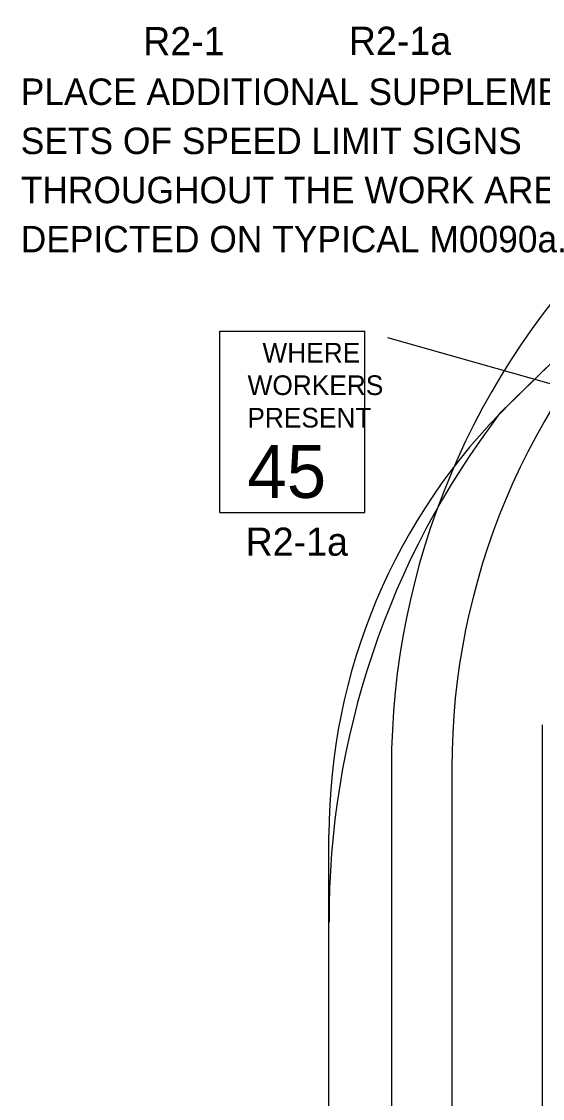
# Model space of a CAD drawing. Extents: x 16735 to 19510, y 5880 to 6929.
# Drawn here: x 16739.9 to 16877.8, y 6269.8 to 6554.7 of the extents above; entities that cross this region are included whole.
import ezdxf

# ---------------------------------------------------------------- set-up
doc = ezdxf.new("R2010")
doc.units = 0
for name, color, linetype in [('ALI_LEGAL_EX', 7, 'Continuous'), ('BORDER', 7, 'Continuous'), ('SCRATCH_LEVEL_A', 7, 'Continuous'), ('TRAFFIC_SIGNS_PR', 7, 'Continuous')]:
    doc.layers.add(name, color=color, linetype=linetype)

msp = doc.modelspace()

# ---------------------------------------------------------------- linework, layer by layer
at = {"layer": 'ALI_LEGAL_EX'}
for p, q in [((16866.49, 6450.99), (17215.7, 6793.27)), ((16821.31, 5959.79), (16821.31, 6316.41))]:
    msp.add_line(p, q, dxfattribs=at)
msp.add_arc((17042.09, 6317.17), 220.78, 142.6899, 180.1983, dxfattribs=at)
at = {"layer": 'BORDER'}
for p, q in [((16867.78, 6452.26), (17214.45, 6792.05)), ((16837.83, 6357.23), (16837.83, 5977.53)), ((16853.83, 6357.23), (16853.83, 5977.53)), ((16821.31, 5959.79), (16821.31, 6339.5)), ((16877.83, 5977.53), (16877.83, 6334.14))]:
    msp.add_line(p, q, dxfattribs=at)
for points in [[(16877.83, 6277.53), (16877.83, 6368.68)], [(16877.83, 6277.53), (16877.83, 6302.53)]]:
    msp.add_lwpolyline(points, dxfattribs=at)
for centre, radius, start, end in [((17037.83, 6357.23), 200, 134.4258, 179.9999), ((17037.83, 6357.23), 184, 134.4258, 180.0001), ((16981.31, 6339.5), 160, 134.3562, 180.0001)]:
    msp.add_arc(centre, radius, start, end, dxfattribs=at)
at = {"layer": 'SCRATCH_LEVEL_A'}
for p, q in [((16792.38, 6472.83), (16830.78, 6472.83)), ((16792.38, 6424.83), (16792.38, 6472.83)), ((16830.78, 6424.83), (16830.78, 6472.83)), ((16792.38, 6424.83), (16830.78, 6424.83))]:
    msp.add_line(p, q, dxfattribs=at)
at = {"layer": 'TRAFFIC_SIGNS_PR'}
msp.add_line((16953.87, 6437.75), (16836.92, 6471.08), dxfattribs=at)

# ---------------------------------------------------------------- texts
at = {"layer": 'SCRATCH_LEVEL_A'}
for s, height, p in [('R2-1', 7.44, (16772.11, 6545.84)), ('R2-1a', 7.44, (16826.55, 6545.93)), ('PLACE ADDITIONAL SUPPLEMENTAL', 7, (16739.7, 6532.67)), ('SETS OF SPEED LIMIT SIGNS', 7, (16739.7, 6519.67)), ('THROUGHOUT THE WORK AREA AS', 7, (16739.7, 6506.67)), ('DEPICTED ON TYPICAL M0090a.', 7, (16739.7, 6493.67)), ('WHERE', 5.2, (16803.69, 6464.51)), ('WORKERS', 5.2, (16799.76, 6455.91)), ('PRESENT', 5.2, (16799.7, 6447.31)), ('45', 14.031, (16799.69, 6428.68)), ('R2-1a', 7.44, (16799.23, 6413.39))]:
    msp.add_text(s, height=height, dxfattribs=at).set_placement(p)

doc.saveas('drawing.dxf')
